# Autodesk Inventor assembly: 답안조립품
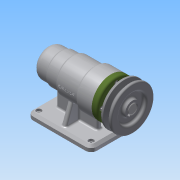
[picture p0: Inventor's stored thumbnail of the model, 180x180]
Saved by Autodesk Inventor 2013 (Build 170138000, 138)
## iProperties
Created: 2016-06
Part Number: 답안조립품
Document SubType Name: Assembly
Designer: Administrator
Author: Administrator
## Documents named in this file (12)
- C:\Users\Administrator\Desktop\460608V1019\답안조립품.iam
- C:\Users\Administrator\Desktop\460608V1019\본체.ipt
- C:\Users\Administrator\Desktop\460608V1019\460608V1019\베어링 51202.ipt
- C:\Users\Administrator\Desktop\460608V1019\460608V1019\어댑터슬리브.ipt
- C:\Users\Administrator\Desktop\460608V1019\460608V1019\축.ipt
- C:\Users\Administrator\Desktop\460608V1019\460608V1019\볼트 M4 x 12.ipt
- C:\Users\Administrator\Desktop\460608V1019\460608V1019\베어링 6004.ipt
- C:\Users\Administrator\Desktop\460608V1019\460608V1019\커버.ipt
- C:\Users\Administrator\Desktop\460608V1019\460608V1019\멈춤나사 M3x8.ipt
- C:\Users\Administrator\Desktop\460608V1019\460608V1019\오일 실.ipt
- C:\Users\Administrator\Desktop\460608V1019\460608V1019\키 5 x 5 x 16.ipt
- C:\Users\Administrator\Desktop\460608V1019\460608V1019\V벨트풀리.ipt
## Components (6 placed, 2 different names)
1. ISO 4762 M4 x 12:1
2. V벨트풀리:1
3. ISO 4762 M4 x 12:2
4. ISO 4762 M4 x 12:3
5. ISO 4762 M4 x 12:4
6. ISO 4762 M4 x 12:5
